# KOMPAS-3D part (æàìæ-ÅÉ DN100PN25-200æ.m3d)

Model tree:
1. Объединить компоненты:1  (labels: СЕНС-ПР DN100PN25-200С)

Referenced files in D:\Савин\!СЕНСОР\3D для заказчика\!Новый перечень\СЕНС-ПР\2. СЕНС-ПР-200С\DN100\: СЕНС-ПР DN100PN25-200С.a3d
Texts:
  СЕНС-ПР DN100PN25-200С
  ООО НПП Сенсор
